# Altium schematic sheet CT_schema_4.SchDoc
size 334 x 183 mm
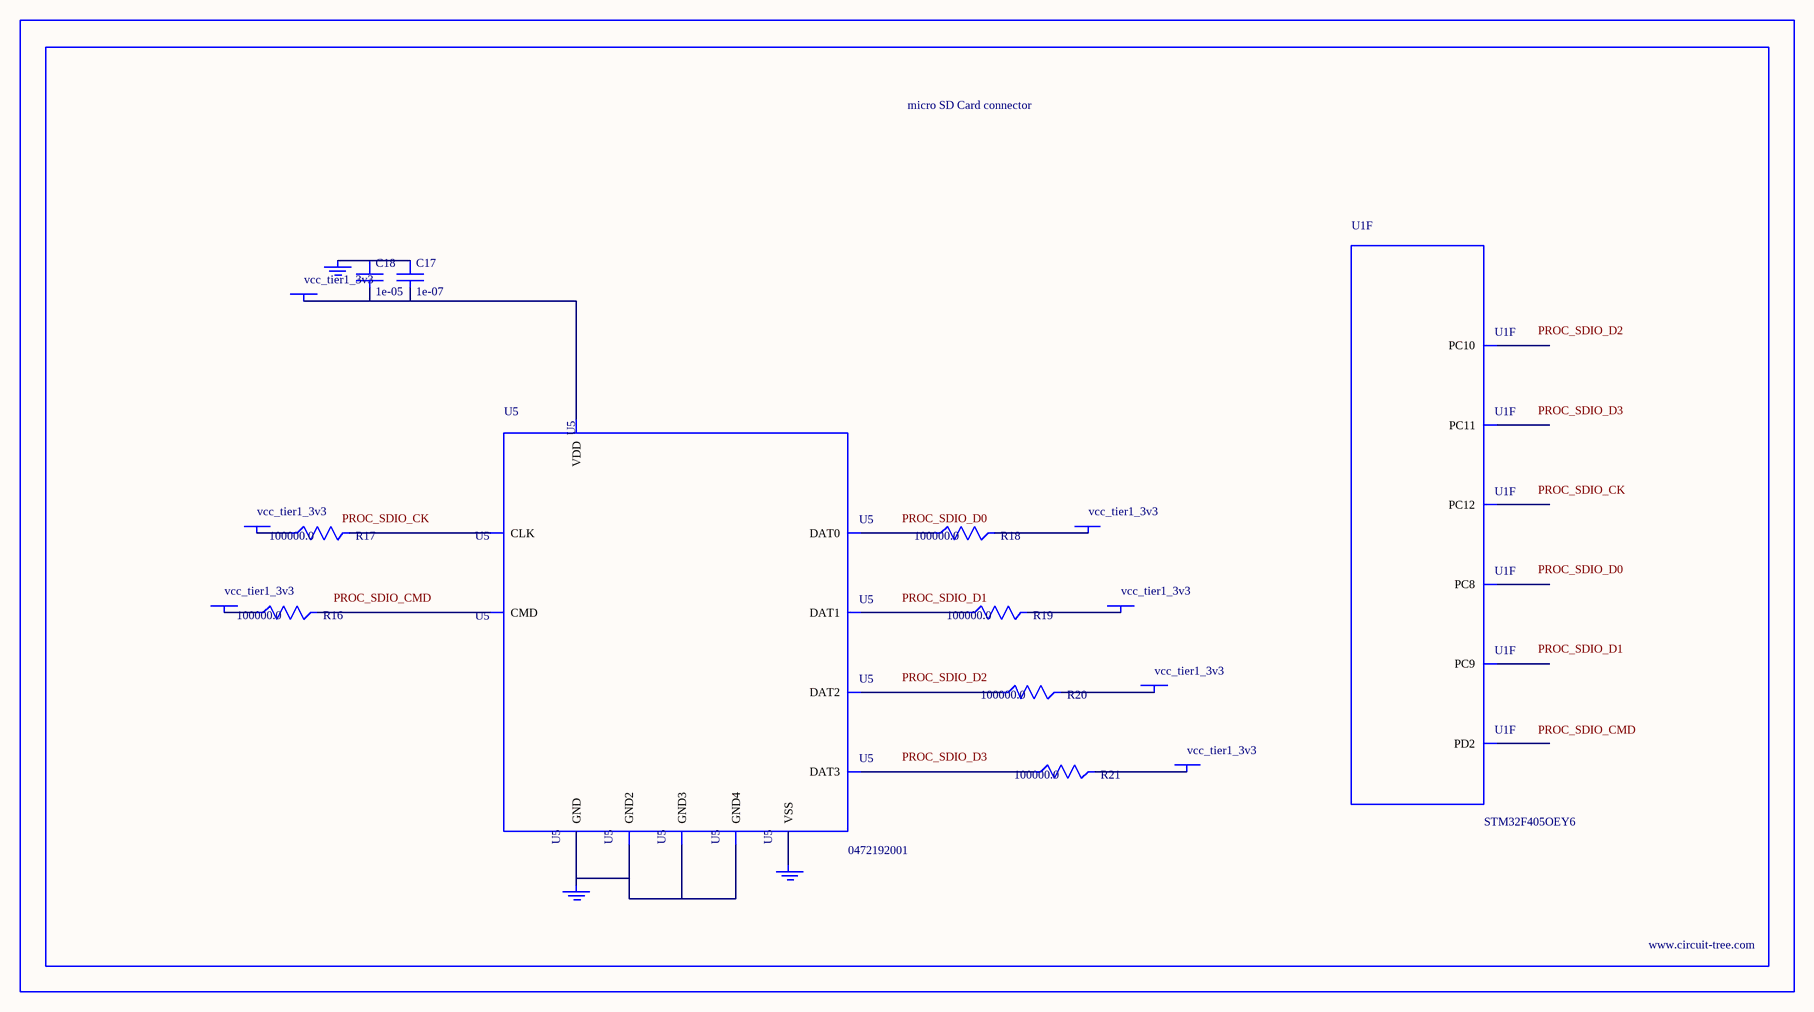
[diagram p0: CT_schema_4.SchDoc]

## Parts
BORDER3  (no value)
C17  1e-07  [C0402]
C18  1e-05  [C0805]
GND_INSTANCE_3_0  (no value)
GND_INSTANCE_3_1  (no value)
GND_INSTANCE_3_2  (no value)
POWER_INSTANCE_3_0  vcc_tier1_3v3
POWER_INSTANCE_3_1  vcc_tier1_3v3
POWER_INSTANCE_3_2  vcc_tier1_3v3
POWER_INSTANCE_3_3  vcc_tier1_3v3
POWER_INSTANCE_3_4  vcc_tier1_3v3
POWER_INSTANCE_3_5  vcc_tier1_3v3
POWER_INSTANCE_3_6  vcc_tier1_3v3
R16  100000.0  [R0603]
R17  100000.0  [R0603]
R18  100000.0  [R0603]
R19  100000.0  [R0603]
R20  100000.0  [R0603]
R21  100000.0  [R0603]
U1  STM32F405OEY6  [WLCSP90]  (part F of 8)
U5  0472192001  [MOLEX_47219-2001]

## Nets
NetC17_1: C17.1 C18.1 GND_INSTANCE_3_0.0(GND)
NetC17_2: C17.2 C18.2 POWER_INSTANCE_3_3.0(PWR) U5.4(VDD)
NetGND_INSTANCE_3_1_0: GND_INSTANCE_3_1.0(GND) U5.6(VSS)
NetGND_INSTANCE_3_2_0: GND_INSTANCE_3_2.0(GND) U5.G1(GND) U5.G2(GND2) U5.G3(GND3) U5.G4(GND4)
NetPOWER_INSTANCE_3_0_0: POWER_INSTANCE_3_0.0(PWR) R20.2
NetPOWER_INSTANCE_3_1_0: POWER_INSTANCE_3_1.0(PWR) R21.2
NetPOWER_INSTANCE_3_2_0: POWER_INSTANCE_3_2.0(PWR) R16.1
NetPOWER_INSTANCE_3_4_0: POWER_INSTANCE_3_4.0(PWR) R17.1
NetPOWER_INSTANCE_3_5_0: POWER_INSTANCE_3_5.0(PWR) R18.2
NetPOWER_INSTANCE_3_6_0: POWER_INSTANCE_3_6.0(PWR) R19.2
NetR16_2: R16.2 U5.3(CMD)
NetR17_2: R17.2 U5.5(CLK)
NetR18_1: R18.1 U5.7(DAT0)
NetR19_1: R19.1 U5.8(DAT1)
NetR20_1: R20.1 U5.1(DAT2)
NetR21_1: R21.1 U5.2(DAT3)

Not connected (* = marked no-connect by the designer): U1 A3(PC12) B4(PD2) C4(PC11) D5(PC10) E2(PC8) E3(PC9)

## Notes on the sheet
- Labels drawn without touching a wire or pin: PROC_SDIO_CK, PROC_SDIO_CMD, PROC_SDIO_D0, PROC_SDIO_D1, PROC_SDIO_D2, PROC_SDIO_D3

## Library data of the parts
BORDER3 = BORDER_PAGE3
C17 = C0402C104K3RACTU
C18 = C0805C106K8RACTU
GND_INSTANCE_3_0-GND_INSTANCE_3_2 = GND
POWER_INSTANCE_3_0-POWER_INSTANCE_3_6 = PWR
R16-R21 = RC0603JR-07100KL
